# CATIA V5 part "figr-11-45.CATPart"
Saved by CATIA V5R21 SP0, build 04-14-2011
Part number: Part1
Bounding box of the stored display mesh (mm): x -59 to 59, y -60 to 210, z -30 to 39.8
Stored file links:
  D:\CATIA V5R21 E-RESOURCES\CATIA-V5R21\catia-v5r21-prt\c11-catia-v5r21-prt\c11-catia-v5r21-figr-11-45.CATPart
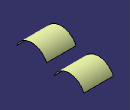
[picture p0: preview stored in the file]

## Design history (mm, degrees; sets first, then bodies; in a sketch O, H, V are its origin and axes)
AxisSystem1: origin (0, 0, 0), X (1, 0, 0), Y (0, 1, 0), Z (0, 0, 1)
AxisSystem2: origin (0, 150, -30), X (1, 0, 0), Y (0, 1, 0), Z (0, 0, 1)
Set1
  Extrude1: Element1 Sketch2, Lim1 59, Lim2 59, Direction yz-plane
  Sketch1 on yz-plane, origin (0, 0, 0), H (0, 1, 0), V (0, 0, 1)
    point P1 (150, -30)
  AxisToAxis1: ToTransfor Extrude1, AxisOrigin AxisSystem1, Axis AxisSystem2
Body1 (main body)
  Sketch2 on yz-plane, origin (0, 0, 0), H (0, 1, 0), V (0, 0, 1)
    arc A1 centre (0, -25) radius 65 from (-60, 0) to (60, 0) cw
    point P2 (-60, 0)
    point P3 (60, 0)
    coincidence: P2 H, P3 H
